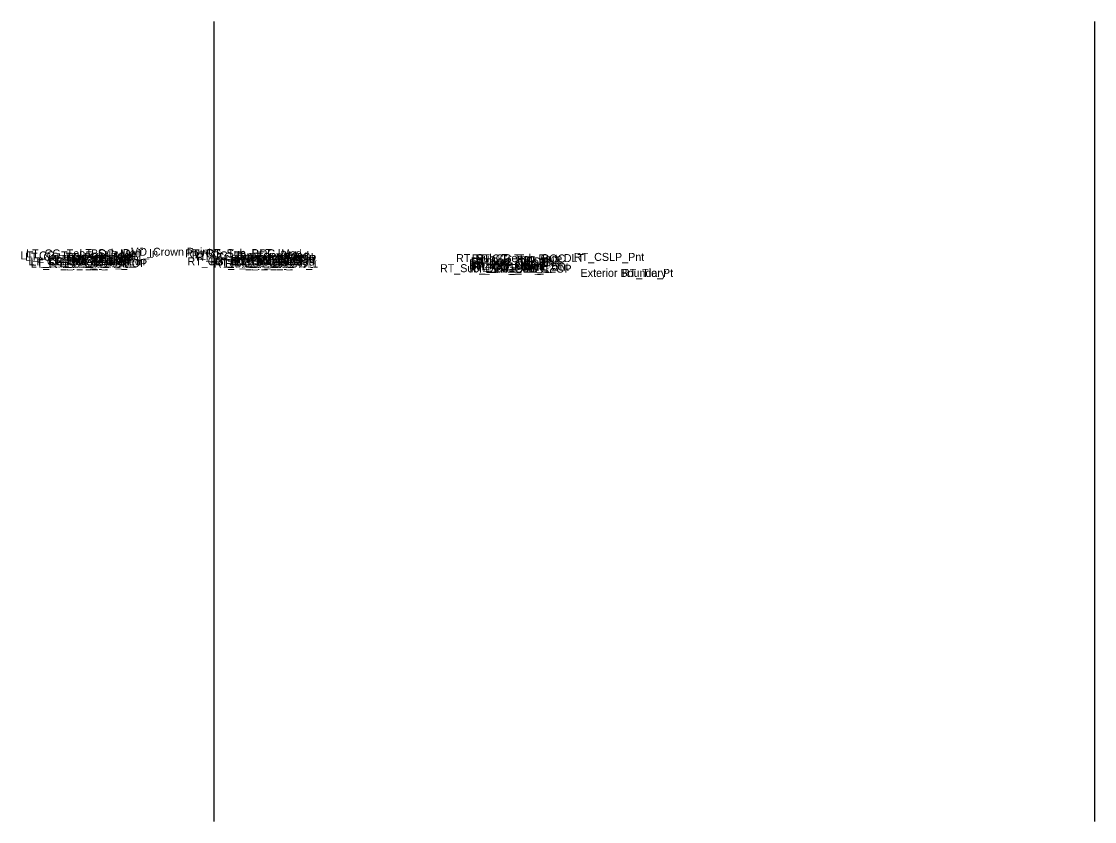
# Model space of a CAD drawing. Extents: x 0 to 6300, y -50 to 9550.
# Drawn here: x 2126 to 2260, y 4950 to 5050 of the extents above; entities that cross this region are included whole.
import ezdxf

# ---------------------------------------------------------------- set-up
doc = ezdxf.new("R2010")
doc.units = 0
for name, color, linetype in [('Default', 7, 'Continuous'), ('Prop XS Exc Vertical Line 2', 7, 'Continuous'), ('Prop XS Exc Vertical Line 3', 7, 'Continuous')]:
    doc.layers.add(name, color=color, linetype=linetype)

msp = doc.modelspace()

# ---------------------------------------------------------------- linework, layer by layer
at = {"layer": 'Prop XS Exc Vertical Line 2'}
msp.add_line((2150, 5050), (2150, 4950), dxfattribs=at)
at = {"layer": 'Prop XS Exc Vertical Line 3'}
msp.add_line((2260, 5050), (2260, 4950), dxfattribs=at)

# ---------------------------------------------------------------- texts
at = {"layer": 'Default'}
for s, p in [('LT_CG_Top_Face_Med', (2125.87, 5020.26)), ('LT_CG_Top_Gut_Med', (2126.42, 5020.09)), ('LT_CG_Top_BOC_Med', (2126.57, 5020.51)), ('LT_CG_Bot_BOC_Med', (2126.85, 5019.52)), ('LT_CG_Bot_IE_Med', (2127.09, 5019.49)), ('LT_PV2_OEEOP', (2129.29, 5019.83)), ('LT_PV3_OEEOP', (2129.29, 5019.58)), ('LT_PV2_IEEOP', (2130.05, 5019.83)), ('LT_CG1_Shelf_In', (2130.71, 5019.53)), ('LT_PV2_PGL', (2131.26, 5019.83)), ('LT_PV1_PGL', (2131.5, 5020.08)), ('LT_Sub_DLT_In', (2133.22, 5020.55)), ('MD_Crown Point', (2139.58, 5020.71)), ('RT_CG_Top_BOC_Med', (2146.43, 5020.51)), ('RT_CG_Bot_BOC_Med', (2146.71, 5019.52)), ('RT_CG_Top_Face_Med', (2147.25, 5020.26)), ('RT_CG_Top_Gut_Med', (2147.8, 5020.09)), ('RT_Sub_DLT_In', (2149.07, 5020.55)), ('RT_CG1_Shelf_In', (2149.57, 5019.53)), ('RT_CG_Bot_IE_Med', (2149.98, 5019.49)), ('RT_PV2_OEEOP', (2152.17, 5019.83)), ('RT_PV3_OEEOP', (2152.17, 5019.58)), ('RT_PV2_IEEOP', (2152.93, 5019.83)), ('RT_PV2_PGL', (2154.15, 5019.83)), ('RT_PV1_PGL', (2154.38, 5020.08)), ('RT_Sub_Trench_Out_DLT', (2180.26, 5019.92)), ('RT_CG_Top_Face', (2182.22, 5019.88)), ('RT_CG_Top_BOC', (2182.69, 5019.88)), ('RT_CSLP_Pnt', (2194.98, 5020.07)), ('LT_Sub_IEOT_CG_1', (2127.13, 5019.24)), ('LT_Sub_OEEOP', (2129.33, 5019.2)), ('LT_Sub_IEEOP', (2130.09, 5019.2)), ('LT_Sub_PGL', (2131.31, 5019.2)), ('LT_Sub_IEOP', (2133.05, 5019.29)), ('RT_Sub_IEOT_CG_1', (2150.01, 5019.24)), ('RT_Sub_IEOP', (2151.42, 5019.29)), ('RT_Sub_OEEOP', (2152.21, 5019.2)), ('RT_Sub_IEEOP', (2152.97, 5019.2)), ('RT_Sub_PGL', (2154.19, 5019.2)), ('RT_Sub_OEOT_CG_1', (2178.25, 5018.66)), ('RT_PV2_OEOT', (2181.87, 5019.25)), ('RT_PV3_OEOT', (2181.87, 5019)), ('RT_Sub_OEOT', (2181.92, 5018.62)), ('RT_PV1_OEOT', (2182.11, 5019.5)), ('RT_CG_Bot_IE', (2182.22, 5018.91)), ('RT_CG1_Shelf_Out', (2182.36, 5018.85)), ('RT_CG_Top_Gut', (2182.75, 5019.38)), ('RT_CG_Bot_BOC', (2182.97, 5018.86)), ('RT_Sub_OEOP', (2185.17, 5018.6)), ('Exterior Boundary', (2195.81, 5018.07)), ('RT_Tie_Pt', (2200.97, 5018.07))]:
    msp.add_text(s, height=1, dxfattribs=at).set_placement(p)

doc.saveas('drawing.dxf')
